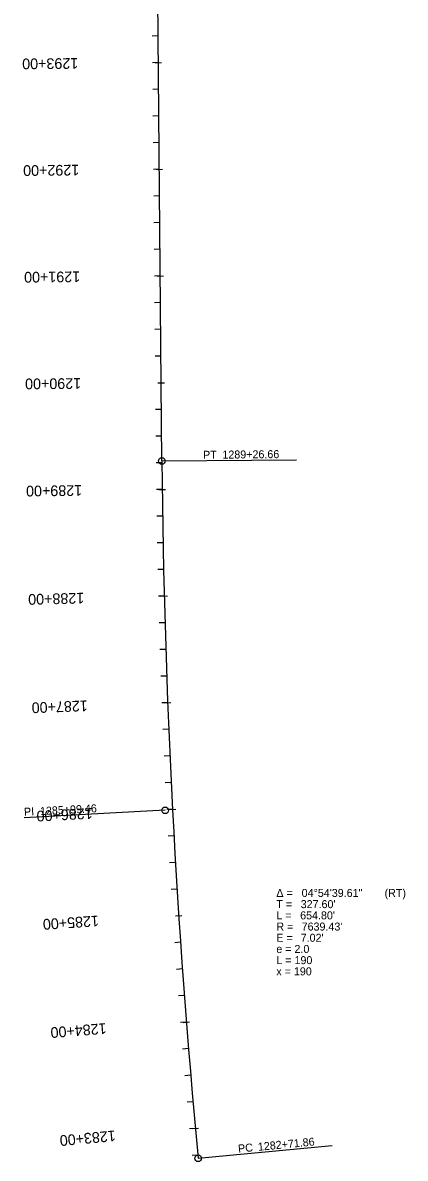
# Model space of a CAD drawing. Extents: x 19548215 to 19548727, y 7547983 to 7562114.
# Drawn here: x 19548324 to 19548683, y 7550274 to 7551338 of the extents above; entities that cross this region are included whole.
import ezdxf

# ---------------------------------------------------------------- set-up
doc = ezdxf.new("R2010")
doc.units = 0
for name, color, linetype in [('Contours Major', 7, 'Continuous'), ('Contours Minor', 7, 'Continuous'), ('Default', 7, 'Continuous'), ('TextAlignment', 7, 'Continuous'), ('TextAlignmentSml', 7, 'Continuous')]:
    doc.layers.add(name, color=color, linetype=linetype)

msp = doc.modelspace()

# ---------------------------------------------------------------- linework, layer by layer
at = {"layer": 'Contours Major'}
for p, q in [((19548451.3, 7551300.6), (19548445.9, 7551300.5)), ((19548452.2, 7551200.6), (19548446.8, 7551200.5)), ((19548453.1, 7551100.6), (19548447.7, 7551100.5)), ((19548451, 7551000.5), (19548457.1, 7551000.6)), ((19548455, 7550900.6), (19548449.5, 7550900.5)), ((19548456.9, 7550800.6), (19548451.4, 7550800.5)), ((19548460.1, 7550700.6), (19548454.7, 7550700.4)), ((19548464.6, 7550600.7), (19548459.2, 7550600.5)), ((19548467.4, 7550500.7), (19548473.5, 7550501.1)), ((19548477.6, 7550401.2), (19548472.2, 7550400.8)), ((19548486, 7550301.5), (19548480.6, 7550301))]:
    msp.add_line(p, q, dxfattribs=at)
at = {"layer": 'Contours Minor'}
msp.add_line((19548454.7, 7550927.2), (19548445, 7552002.1), dxfattribs=at)
msp.add_arc((19556093.8, 7550996.1), 7639.4, 180.51637, 185.42737, dxfattribs=at)
at = {"layer": 'Default'}
msp.add_line((19548454.7, 7550927.2), (19548445, 7552002.1), dxfattribs=at)
msp.add_arc((19556093.8, 7550996.1), 7639.4, 180.51637, 185.42737, dxfattribs=at)
at = {"layer": 'TextAlignment'}
for p, q in [((19548454.7, 7550927.2), (19548580.7, 7550928.4)), ((19548580.7, 7550928.4), (19548580.7, 7550928.4)), ((19548457.7, 7550599.7), (19548325.8, 7550592.8)), ((19548325.8, 7550592.8), (19548325.8, 7550592.8)), ((19548488.6, 7550273.5), (19548614.1, 7550285.4)), ((19548614.1, 7550285.4), (19548614.1, 7550285.4))]:
    msp.add_line(p, q, dxfattribs=at)
for centre in [(19548454.7, 7550927.2), (19548457.7, 7550599.7), (19548488.6, 7550273.5)]:
    msp.add_circle(centre, 3.12, dxfattribs=at)
at = {"layer": 'TextAlignmentSml'}
for p, q in [((19548451.1, 7551325.6), (19548445.7, 7551325.5)), ((19548448.3, 7551300.5), (19548454.4, 7551300.6)), ((19548451.6, 7551275.6), (19548446.1, 7551275.5)), ((19548451.8, 7551250.6), (19548446.3, 7551250.5)), ((19548452, 7551225.6), (19548446.6, 7551225.5)), ((19548449.2, 7551200.5), (19548455.3, 7551200.6)), ((19548452.5, 7551175.6), (19548447, 7551175.5)), ((19548452.7, 7551150.6), (19548447.2, 7551150.5)), ((19548452.9, 7551125.6), (19548447.5, 7551125.5)), ((19548450.1, 7551100.5), (19548456.2, 7551100.6)), ((19548453.4, 7551075.6), (19548447.9, 7551075.5)), ((19548453.6, 7551050.6), (19548448.1, 7551050.5)), ((19548453.8, 7551025.6), (19548448.4, 7551025.5)), ((19548451, 7551000.5), (19548457.1, 7551000.6)), ((19548454.3, 7550975.6), (19548448.8, 7550975.5)), ((19548454.5, 7550950.6), (19548449, 7550950.5)), ((19548454.7, 7550925.6), (19548449.3, 7550925.5)), ((19548451.9, 7550900.5), (19548458.1, 7550900.6)), ((19548455.3, 7550875.6), (19548449.9, 7550875.5)), ((19548455.8, 7550850.6), (19548450.3, 7550850.5)), ((19548456.3, 7550825.6), (19548450.8, 7550825.5)), ((19548453.8, 7550800.5), (19548460, 7550800.7)), ((19548457.6, 7550775.6), (19548452.1, 7550775.4)), ((19548458.3, 7550750.6), (19548452.9, 7550750.4)), ((19548459.2, 7550725.6), (19548453.7, 7550725.4)), ((19548457.1, 7550700.5), (19548463.2, 7550700.8)), ((19548461.1, 7550675.7), (19548455.7, 7550675.4)), ((19548462.2, 7550650.7), (19548456.8, 7550650.4)), ((19548463.4, 7550625.7), (19548457.9, 7550625.5)), ((19548461.6, 7550600.6), (19548467.7, 7550600.9)), ((19548466, 7550575.8), (19548460.5, 7550575.5)), ((19548467.4, 7550550.8), (19548461.9, 7550550.5)), ((19548468.9, 7550525.9), (19548463.4, 7550525.5)), ((19548467.4, 7550500.7), (19548473.5, 7550501.1)), ((19548472.1, 7550476), (19548466.7, 7550475.6)), ((19548473.9, 7550451), (19548468.4, 7550450.6)), ((19548475.7, 7550426.1), (19548470.2, 7550425.7)), ((19548474.5, 7550400.9), (19548480.6, 7550401.4)), ((19548479.6, 7550376.3), (19548474.1, 7550375.8)), ((19548481.7, 7550351.3), (19548476.2, 7550350.9)), ((19548483.8, 7550326.4), (19548478.4, 7550326)), ((19548483, 7550301.3), (19548489.1, 7550301.8)), ((19548488.3, 7550276.6), (19548482.9, 7550276.1))]:
    msp.add_line(p, q, dxfattribs=at)

# ---------------------------------------------------------------- texts
at = {"layer": 'Contours Major'}
for s, rotation, p in [('1290+00', 180.5164, (19548379, 7551004.9)), ('1285+00', 183.7163, (19548395.3, 7550501.1))]:
    msp.add_text(s, height=10.02, rotation=rotation, dxfattribs=at).set_placement(p)
at = {"layer": 'TextAlignment'}
for s, rotation, p in [('PT', 0.5164, (19548493.3, 7550929.2)), ('1289+26.66', 0.5164, (19548511.4, 7550929.4)), ('PI ', 2.9719, (19548325.7, 7550594.5)), ('1285+99.46', 2.9719, (19548340.7, 7550595.2)), ('1282+71.86', 5.4274, (19548545, 7550280.5)), ('PC', 5.4274, (19548526.4, 7550278.8))]:
    msp.add_text(s, height=7.5, rotation=rotation, dxfattribs=at).set_placement(p)
for s, p in [('Δ = ', (19548561.9, 7550518.5)), ('04°54\'39.61"', (19548585.6, 7550518.5)), (' (RT)', (19548660.5, 7550518.5)), ('T = ', (19548561.9, 7550508)), ("327.60'", (19548584.7, 7550508)), ('L = ', (19548561.9, 7550497.5)), ("654.80'", (19548584.2, 7550497.5)), ('R = ', (19548561.9, 7550487)), ("7639.43'", (19548585.6, 7550487)), ('E = ', (19548561.9, 7550476.5)), ("7.02'", (19548584.7, 7550476.5)), ('e = 2.0', (19548561.9, 7550466)), ('L = 190', (19548561.9, 7550455.5)), ('x = 190', (19548561.9, 7550445))]:
    msp.add_text(s, height=7.5, dxfattribs=at).set_placement(p)
at = {"layer": 'TextAlignmentSml'}
for s, rotation, p in [('1293+00', 180.5164, (19548376.3, 7551304.9)), ('1292+00', 180.5164, (19548377.2, 7551204.9)), ('1291+00', 180.5164, (19548378.1, 7551104.9)), ('1290+00', 180.5164, (19548379, 7551004.9)), ('1289+00', 180.7163, (19548379.9, 7550904.6)), ('1288+00', 181.4663, (19548381.8, 7550803.7)), ('1287+00', 182.2163, (19548385, 7550702.8)), ('1286+00', 182.9663, (19548389.5, 7550601.9)), ('1285+00', 183.7163, (19548395.3, 7550501.1)), ('1284+00', 184.4663, (19548402.4, 7550400.3)), ('1283+00', 185.2163, (19548410.9, 7550299.7))]:
    msp.add_text(s, height=10.02, rotation=rotation, dxfattribs=at).set_placement(p)

doc.saveas('drawing.dxf')
